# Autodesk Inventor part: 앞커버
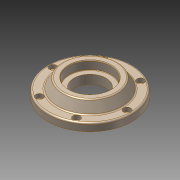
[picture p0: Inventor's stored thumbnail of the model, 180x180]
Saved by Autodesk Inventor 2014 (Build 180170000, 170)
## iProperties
Created: 2013-01
Part Number: 앞커버
Document SubType Name: Modeling
Designer: 한국산업디자인학원[gmhk.co.kr]
Density: 2.71 g/cm^3
Material: 알루미늄 6061
Mass: 321.537 g
Surface Area: 281.944 cm^2
Volume: 118.648 cm^3
Appearance: 알루미늄 - 평지(2)
Author: 한국산업디자인학원[gmhk.co.kr]
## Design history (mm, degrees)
sketch "스케치2"
  geometry: L1 (-55, 0)-(55, 0) reference; L2 (35.98, -6)-(-35.98, -6) reference; L3 (-42.5, -25)-(-42.5, 0) reference; L4 (-37, -6)-(-37, 0); L5 (-55, 0)-(-55, 10); L6 (-55, 10)-(-42.5, 10); L7 (-37, -6)-(-42.5, -6); L8 (-42.5, 10)-(-34.994, 23); L9 (-34.994, 23)-(0, 23); L10 (-55, 0)-(-42.5, 0); L11 (-42.5, -6)-(-42.5, 0); L12 (0, 0)-(0, 23); L13 (0, 0)-(-37, 0)
  constraints: 22 end point, 4 perpendicular, 3 collinear, 2 parallel, 2 point on line, 1 vertical, 2 other
  dimensions: "d2" = 10 distance of L1.start L5.end; "d4" = 120 deg angle of L8 L6; "d5" = 13 distance between parallel lines of L6 L9; "d6" = 74 diameter of L4 L12; "d7" = 85 diameter of L6.end L12
revolve "회전1" sketch "스케치2" stored, may be unused: angle "d8" = 90 deg
fillet "모깎기1" dims "d9" = 2
sketch "스케치3"
  geometry: C1 r 2.067 at (48.5, 0) reference; 1 further point
hole "구멍1" sketch "스케치3" at (48.5, 0) diameter "d10" = 5.5; stored, may be unused: countersink angle "d14" = 90 deg, drill point angle "d16" = 118 deg; dims "d11" = 6, "d12" = 9.5, "d13" = 5.4, "d15" = 8
fillet "모깎기2" dims "d20" = 3
chamfer "모따기1" distance "d21" = 1; stored, may be unused: second distance "d22" = 2, angle "d23" = 45 deg
sketch "스케치4"
  geometry: L1 (-33.84, 23)-(33.84, 23) reference; L2 (34, 0)-(-34, 0) reference; L3 (0, 0)-(0, 23); L4 (27.5, 21.9)-(27.5, 12.1); L5 (27, 11.6)-(21, 11.6); L6 (21, 11.6)-(21, 0); L7 (27.5, 21.9)-(28.135, 23); A1 r 0.5 centre (27, 12.1) between (27, 11.6) and (27.5, 12.1)
  constraints: 10 end point, 2 perpendicular, 2 point on circle, 2 point on line, 2 tangent, 1 centre point, 1 midpoint, 1 parallel
  dimensions: "d24" = 11.4 distance between parallel lines of L5 L1; "d25" = 1.1 distance from line of L4.start L1; "d26" = 30 deg angle of L7 L4; "d27" = 0.5 radius of A1; "d28" = 55 diameter of L4 L3; "d29" = 42 diameter of L6 L3
revolve "회전2" sketch "스케치4" stored, may be unused: angle "d30" = 90 deg
node "솔리드1"
pattern_circular "원형 패턴1" dims angle "d18" = 360 deg
node "참조1"
node "참조2"
node "참조3"
